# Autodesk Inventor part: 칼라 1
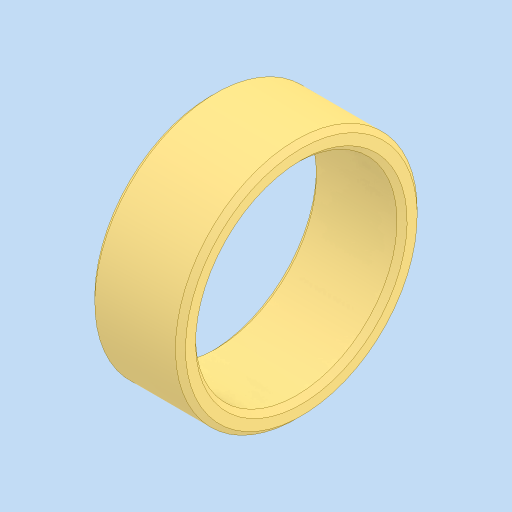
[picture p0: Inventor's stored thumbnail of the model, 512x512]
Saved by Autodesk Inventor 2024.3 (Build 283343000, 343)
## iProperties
Created: 2025-11
Part Number: 칼라 1
Material: 강철, 연강
Document SubType Name: Modeling
Designer: PC2-02
Density: 7.85 g/cm^3
Appearance: 기본값
Author: jhkim
Sending System: Autodesk Inventor 2026
Preprocessor: ST-DEVELOPER v20.1
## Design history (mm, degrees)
node "칼라 11"
node "솔리드2"
node "솔리드1"
